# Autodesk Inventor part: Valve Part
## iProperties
Created: 2010-02
Part Number: Valve Part
Document SubType Name: Modeling
Designer: jgehrig
Density: 1 g/cm^3
Author: jgehrig
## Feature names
1. Extrusion1
2. Extrusion2
3. Extrusion3
4. Extrusion4
